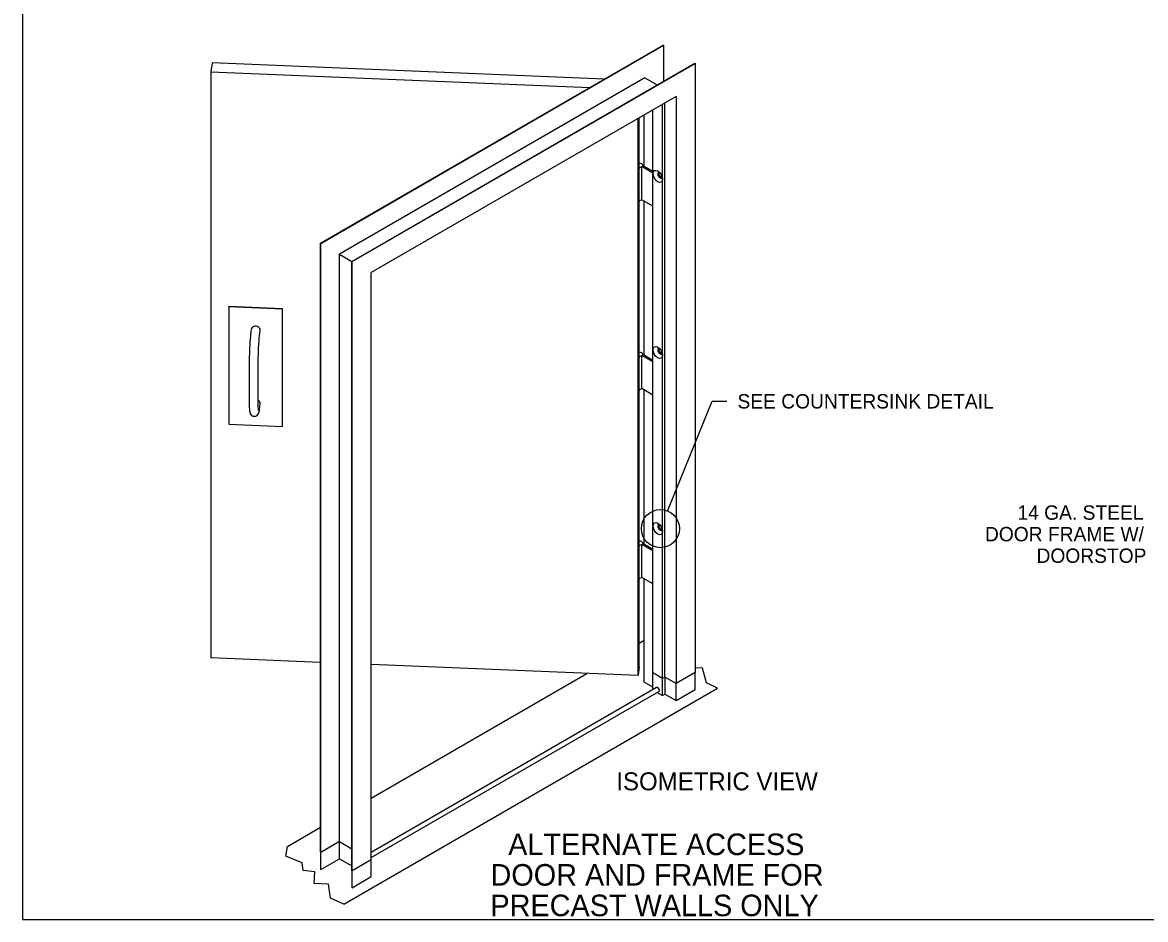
# Model space of a CAD drawing. Extents: x 99862 to 103151, y 100000 to 105076.
# Drawn here: x 99862 to 101113, y 103000 to 103998 of the extents above; entities that cross this region are included whole.
import ezdxf

# ---------------------------------------------------------------- set-up
doc = ezdxf.new("R2010")
doc.units = 0
for name, color, linetype in [('Level 1', 7, 'Continuous'), ('Level 15', 7, 'Continuous'), ('Level 18', 7, 'Continuous'), ('Level 20', 7, 'Continuous'), ('Level 5', 7, 'Continuous'), ('Level 60', 7, 'Continuous')]:
    doc.layers.add(name, color=color, linetype=linetype)

msp = doc.modelspace()

# ---------------------------------------------------------------- linework, layer by layer
at = {"layer": 'Level 1'}
msp.add_lwpolyline([(99862, 102999.5), (103151, 102999.5), (103151, 105075.5), (99862, 105075.5)], close=True, dxfattribs=at)
at = {"layer": 'Level 15'}
for p, q in [((100580.4, 103454.1), (100630.2, 103576.2)), ((100630.2, 103576.2), (100646.2, 103576.2))]:
    msp.add_line(p, q, dxfattribs=at)
msp.add_circle((100572.4, 103434.5), 21.2, dxfattribs=at)
at = {"layer": 'Level 18'}
for p, q in [((100193.8, 103752.1), (100575.6, 103972.6)), ((100194.1, 103751.9), (100576, 103972.4)), ((100576, 103972.4), (100575.6, 103972.6)), ((100576, 103972.4), (100576, 103932.4)), ((100073.2, 103952.8), (100071.9, 103942.8)), ((100510, 103934.7), (100073.2, 103952.8)), ((100228.8, 103731.9), (100610.6, 103952.4)), ((100229.1, 103731.7), (100611, 103952.2)), ((100610.6, 103952.4), (100611, 103952.2)), ((100611, 103952.2), (100611, 103274.5)), ((100071.9, 103942.8), (100071.9, 103290.6)), ((100071.9, 103942.8), (100493.7, 103925.3)), ((100555.1, 103936.3), (100215, 103739.9)), ((100555.1, 103936.3), (100568.9, 103928.3)), ((100589.8, 103915.4), (100250.4, 103719.5)), ((100589.8, 103915.4), (100589.8, 103262.2)), ((100574.7, 103267.9), (100574.7, 103906.8)), ((100577.4, 103269.4), (100577.4, 103908.3)), ((100547.5, 103270.9), (100547.5, 103891)), ((100548.7, 103280.9), (100548.7, 103891.7)), ((100554.4, 103837.9), (100554.4, 103895)), ((100564.1, 103274), (100564.1, 103900.6)), ((100548.8, 103836.7), (100547.5, 103826.1)), ((100564.1, 103830.2), (100551.8, 103837.4)), ((100551.8, 103800.6), (100551.8, 103837.4)), ((100552.9, 103838.8), (100564.1, 103832.3)), ((100569.4, 103832.6), (100569.4, 103832.6)), ((100570.8, 103830.2), (100570.8, 103830.2)), ((100573.3, 103825.9), (100573.7, 103826.1)), ((100574.7, 103823.5), (100574.7, 103823.5)), ((100548.8, 103800.1), (100547.5, 103789.3)), ((100564.1, 103793.5), (100551.8, 103800.6)), ((100554.4, 103627.6), (100554.4, 103799.1)), ((100193.8, 103074.4), (100193.8, 103752.1)), ((100194.1, 103751.9), (100193.8, 103752.1)), ((100194.1, 103074.2), (100194.1, 103751.9)), ((100215, 103086.3), (100215, 103739.9)), ((100215, 103739.9), (100228.8, 103731.9)), ((100228.8, 103054.2), (100228.8, 103731.9)), ((100228.8, 103731.9), (100229.1, 103731.7)), ((100229.1, 103054), (100229.1, 103731.7)), ((100250.4, 103066.3), (100250.4, 103719.5)), ((100091.8, 103681.4), (100091.9, 103681.7)), ((100091.8, 103681.4), (100091.8, 103550.7)), ((100151.7, 103678.9), (100091.8, 103681.4)), ((100151.7, 103679.2), (100091.9, 103681.7)), ((100151.7, 103548.6), (100151.7, 103679.2)), ((100151.7, 103678.9), (100151.7, 103679.2)), ((100151.7, 103548.3), (100151.7, 103678.9)), ((100116.8, 103656.3), (100116.1, 103650.5)), ((100126, 103649.3), (100126.7, 103655)), ((100548.8, 103626.6), (100547.5, 103615.8)), ((100564.1, 103620), (100551.8, 103627.1)), ((100551.8, 103590.4), (100551.8, 103627.1)), ((100552.9, 103628.5), (100564.1, 103622)), ((100569.4, 103636.6), (100569.4, 103636.6)), ((100570.8, 103634.2), (100570.8, 103634.2)), ((100573.3, 103629.9), (100573.7, 103630.1)), ((100574.7, 103627.6), (100574.7, 103627.6)), ((100114.6, 103622), (100114.6, 103573.1)), ((100124.6, 103573.1), (100124.6, 103622)), ((100548.8, 103589.9), (100547.5, 103579.1)), ((100564.1, 103583.2), (100551.8, 103590.4)), ((100554.4, 103417.4), (100554.4, 103588.8)), ((100126, 103567.6), (100126.7, 103573.4)), ((100091.8, 103550.7), (100151.7, 103548.3)), ((100151.7, 103548.3), (100151.7, 103548.6)), ((100569.4, 103440.5), (100569.4, 103440.5)), ((100573.3, 103433.8), (100573.7, 103434)), ((100574.7, 103431.4), (100574.7, 103431.4)), ((100548.8, 103416.4), (100547.5, 103405.6)), ((100564.1, 103409.7), (100551.8, 103416.9)), ((100551.8, 103380.1), (100551.8, 103416.9)), ((100552.9, 103418.3), (100564.1, 103411.8)), ((100548.8, 103379.6), (100547.5, 103368.8)), ((100564.1, 103373), (100551.8, 103380.1)), ((100554.4, 103282.7), (100554.4, 103378.6)), ((100193.8, 103285.5), (100071.9, 103290.6)), ((100547.5, 103270.9), (100250.4, 103283.2)), ((100548.7, 103280.9), (100547.5, 103270.9)), ((100574.7, 103267.9), (100564.1, 103274)), ((100564.1, 103255.3), (100564.1, 103274)), ((100577.4, 103269.4), (100574.7, 103267.9)), ((100574.7, 103248.8), (100574.7, 103267.9)), ((100589.8, 103262.2), (100577.4, 103269.4)), ((100577.4, 103269.4), (100577.4, 103250.3)), ((100611, 103274.5), (100589.8, 103262.2)), ((100568.2, 103257.7), (100250.4, 103074.2)), ((100250.4, 103068.4), (100570.7, 103253.3)), ((100589.8, 103243.2), (100589.8, 103262.2)), ((100215, 103086.3), (100194.1, 103074.2)), ((100215, 103086.3), (100228.8, 103078.3)), ((100215, 103067.2), (100215, 103086.3)), ((100194.1, 103074.2), (100193.8, 103074.4)), ((100194.1, 103055.2), (100194.1, 103074.2)), ((100194.1, 103055.2), (100215, 103067.2)), ((100215, 103067.2), (100228.8, 103059.2)), ((100229.1, 103054), (100250.4, 103066.3)), ((100250.4, 103047.2), (100250.4, 103066.3)), ((100228.8, 103054.2), (100229.1, 103054)), ((100229.1, 103034.9), (100229.1, 103054)), ((100229.1, 103034.9), (100250.4, 103047.2))]:
    msp.add_line(p, q, dxfattribs=at)
for points in [[(100564.1, 103258), (100554.4, 103263.6), (100554.4, 103282.7)], [(100568.8, 103252.2), (100574.7, 103248.8), (100577.4, 103250.3), (100589.8, 103243.2), (100611, 103255.4), (100611, 103274.5)], [(100193.8, 103074.4), (100193.8, 103055.4), (100194.1, 103055.2)], [(100228.8, 103054.2), (100228.8, 103035.2), (100229.1, 103034.9)]]:
    msp.add_lwpolyline(points, dxfattribs=at)
for centre, major_axis, ratio, start_param, end_param in [((100549.1, 103838.9), (3.75, 0), 0.57735, 6.227515, 7.962179), ((100549.1, 103838.9), (3.75, 0), 0.57735, 4.623664, 6.227515), ((100572, 103828), (1.87, -3.25), 0.57735, 2.770127, 6.654651), ((100572, 103828), (-1.25, 2.17), 0.57735, 0.000013, 4.152233), ((100572.4, 103828.3), (-1.25, 2.17), 0.57735, 0.170531, 2.971062), ((100572, 103828), (-1.25, 2.17), 0.57735, 5.272545, 6.283199), ((100549.1, 103802.1), (3.75, 0), 0.57735, 4.623664, 5.497787), ((100121.8, 103655.7), (4.96, -0.62), 0.814396, 6.283146, 9.424778), ((100549.1, 103628.6), (3.75, 0), 0.57735, 6.227515, 7.962179), ((100549.1, 103628.6), (3.75, 0), 0.57735, 4.627769, 5.497787), ((100549.1, 103628.6), (3.75, 0), 0.57735, 5.497787, 6.227515), ((100572, 103632.1), (1.87, -3.25), 0.57735, 2.770127, 6.654651), ((100572, 103632.1), (-1.25, 2.17), 0.57735, 0.000008, 4.152233), ((100572.4, 103632.3), (-1.25, 2.17), 0.57735, 0.170531, 2.971062), ((100572, 103632.1), (-1.25, 2.17), 0.57735, 5.272545, 6.283194), ((100119.6, 103622), (5, 0), 0.57735, 6.211436, 6.283188), ((100549.1, 103591.9), (3.75, 0), 0.57735, 4.623664, 5.497787), ((100121.8, 103574), (4.96, -0.62), 0.814396, 6.283185, 7.346876), ((100119.6, 103573.1), (5, 0), 0.57735, 6.211436, 6.283185), ((100572, 103436), (1.87, -3.25), 0.57735, 2.770127, 6.654651), ((100572, 103436), (-1.25, 2.17), 0.57735, 0, 4.152233), ((100572.4, 103436.2), (-1.25, 2.17), 0.57735, 0.170531, 2.971062), ((100572, 103436), (-1.25, 2.17), 0.57735, 5.272545, 6.283185), ((100549.1, 103418.4), (3.75, 0), 0.57735, 6.227515, 7.962179), ((100549.1, 103418.4), (3.75, 0), 0.57735, 4.627769, 5.497787), ((100549.1, 103418.4), (3.75, 0), 0.57735, 5.497787, 6.227515), ((100549.1, 103381.7), (3.75, 0), 0.57735, 4.623664, 5.497787), ((100569.5, 103255.5), (-1.25, 2.17), 0.57735, 3.141569, 6.283185)]:
    msp.add_ellipse(centre, major_axis=major_axis, ratio=ratio, start_param=start_param, end_param=end_param, dxfattribs=at)
for centre in [(100569.4, 103826.5), (100569.4, 103630.6), (100569.4, 103434.5)]:
    msp.add_ellipse(centre, major_axis=(-3.7, 6.41), ratio=0.57735, dxfattribs=at)
for points in [[(100116.1, 103650.5), (100115.8, 103648), (100115, 103639.1), (100114.6, 103627.3), (100114.6, 103622)], [(100124.6, 103622), (100124.6, 103625.3), (100124.8, 103635.5), (100125.6, 103645.8), (100126, 103649.3)], [(100114.6, 103573.1), (100114.6, 103569.9), (100114.7, 103566.5), (100115, 103564.3), (100115.4, 103562.6), (100116.9, 103560.3), (100120.1, 103559.2), (100123.5, 103560.3), (100125.2, 103562.9), (100125.5, 103564.7), (100125.9, 103566.3), (100126, 103567.6)], [(100124.9, 103566.1), (100124.9, 103566.1), (100124.7, 103567), (100124.6, 103570), (100124.6, 103573.1)]]:
    msp.add_open_spline(points, degree=3, dxfattribs=at)
at = {"layer": 'Level 5'}
for p, q in [((100548.7, 103307), (100554.4, 103310.3)), ((100250.4, 103134.7), (100490.3, 103273.2)), ((100219.7, 103016.6), (100635.9, 103256.9)), ((100157.2, 103080.9), (100193.8, 103102.1))]:
    msp.add_line(p, q, dxfattribs=at)
for points in [[(100635.9, 103256.9), (100623.9, 103263), (100619.1, 103279.2), (100611, 103279.5)], [(100219.7, 103016.6), (100204.9, 103023.3), (100202.9, 103038.9), (100186.7, 103039.6), (100187.4, 103052.7), (100174.5, 103053.9), (100173.4, 103062.7), (100155.3, 103070), (100157.2, 103080.9)]]:
    msp.add_lwpolyline(points, dxfattribs=at)
at = {"layer": 'Level 60'}
msp.add_line((99862, 102999.5), (99862, 102999.5), dxfattribs=at)

# ---------------------------------------------------------------- texts
at = {"layer": 'Level 20'}
for s, height, p in [('SEE COUNTERSINK DETAIL', 16, (100658.2, 103568.2)), ('14 GA. STEEL', 16, (100970, 103444.4)), ('DOOR FRAME W/', 16, (100933.8, 103420.4)), ('DOORSTOP', 16, (100991.2, 103396.4)), ('ISOMETRIC VIEW', 20, (100523.3, 103143.3)), ('ALTERNATE ACCESS', 24, (100402.9, 103071.2)), ('DOOR AND FRAME FOR', 24, (100383.2, 103037.2)), ('PRECAST WALLS ONLY', 24, (100383.1, 103003.2))]:
    msp.add_text(s, height=height, dxfattribs=at).set_placement(p)

doc.saveas('drawing.dxf')
